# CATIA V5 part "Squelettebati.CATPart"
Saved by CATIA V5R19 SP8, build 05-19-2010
Part number: Squelettebati
Bounding box of the stored display mesh (mm): x -20 to 0, y 64 to 100, z 60 to 60
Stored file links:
  C:\Users\rcousturie\Desktop\EU_thinkMotion\iao\IAO_MMS_Groupe1\abergami\abergami_catiaInitial\ObjetsInitials\Squelettebati.CATPart
  C:\Users\rcousturie\Desktop\EU_thinkMotion\iao\IAO_MMS_Groupe1\abergami\abergami_catiaInitial\ObjetsInitials\Product2.CATProduct
  C:\Users\rcousturie\Desktop\EU_thinkMotion\iao\IAO_MMS_Groupe1\abergami\abergami_catiaInitial\ObjetsInitials\Squelettedebase.CATPart
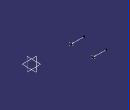
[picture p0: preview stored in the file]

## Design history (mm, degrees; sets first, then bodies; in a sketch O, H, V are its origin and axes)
Set1
  Point1: linked copy from another document
  Point2: linked copy from another document
Set2
  Line1: type Normal, RefPoint Point1, RefSkin yz-plane, Start -20, End 0
  Line2: type Normal, RefPoint Point2, RefSkin yz-plane, Start -20, End 0
Body1 (main body)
